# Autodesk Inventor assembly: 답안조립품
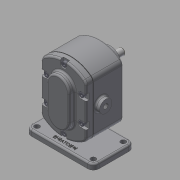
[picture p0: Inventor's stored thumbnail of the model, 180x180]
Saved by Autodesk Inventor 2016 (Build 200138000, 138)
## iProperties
Created: 2019-03
Part Number: 답안조립품
Document SubType Name: Assembly
Designer: Administrator
Author: Administrator
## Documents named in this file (11)
- C:\Users\Administrator\Desktop\490308V1003\답안조립품.iam
- C:\Users\Administrator\Desktop\490308V1003\본체.ipt
- C:\Users\Administrator\Desktop\490308V1003\개스킷.ipt
- C:\Users\Administrator\Desktop\490308V1003\메인축.ipt
- C:\Users\Administrator\Desktop\490308V1003\베어링부시.ipt
- C:\Users\Administrator\Desktop\490308V1003\볼트 M5.ipt
- C:\Users\Administrator\Desktop\490308V1003\서브축.ipt
- C:\Users\Administrator\Desktop\490308V1003\스퍼기어.ipt
- C:\Users\Administrator\Desktop\490308V1003\오일 실 16 28 7.ipt
- C:\Users\Administrator\Desktop\490308V1003\커버.ipt
- C:\Users\Administrator\Desktop\490308V1003\키 6 x 6 x 18.ipt
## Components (1 placed, 1 different names)
1. 개스킷:1
